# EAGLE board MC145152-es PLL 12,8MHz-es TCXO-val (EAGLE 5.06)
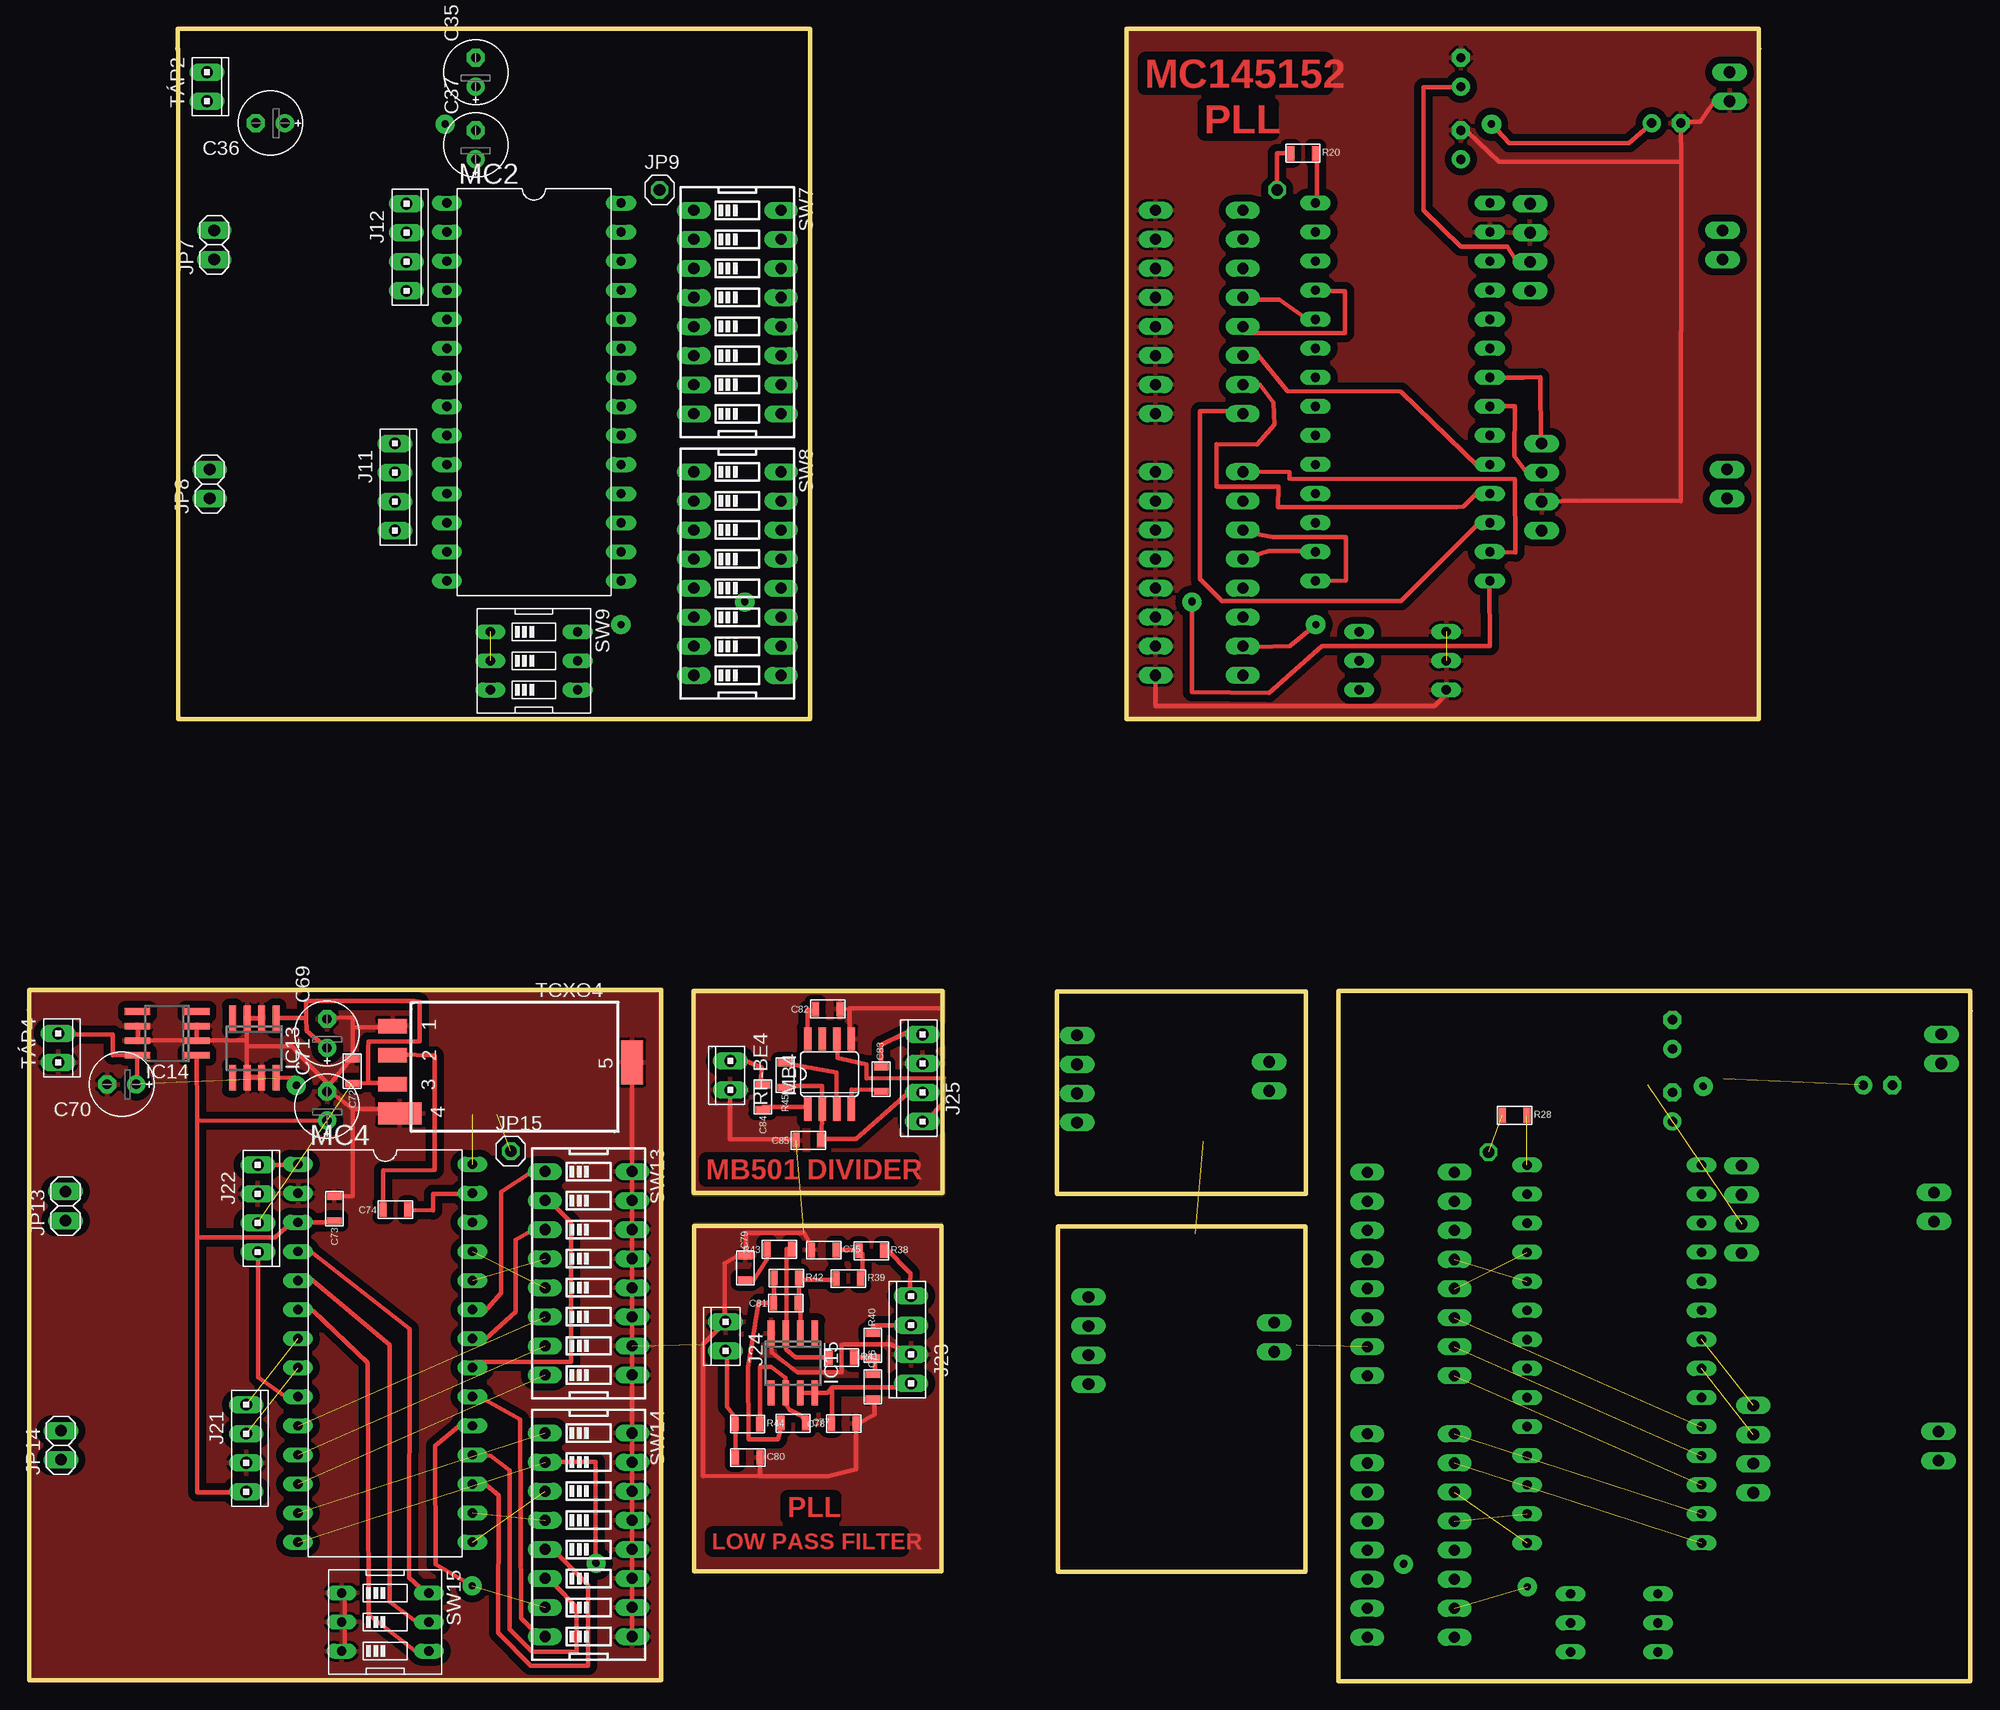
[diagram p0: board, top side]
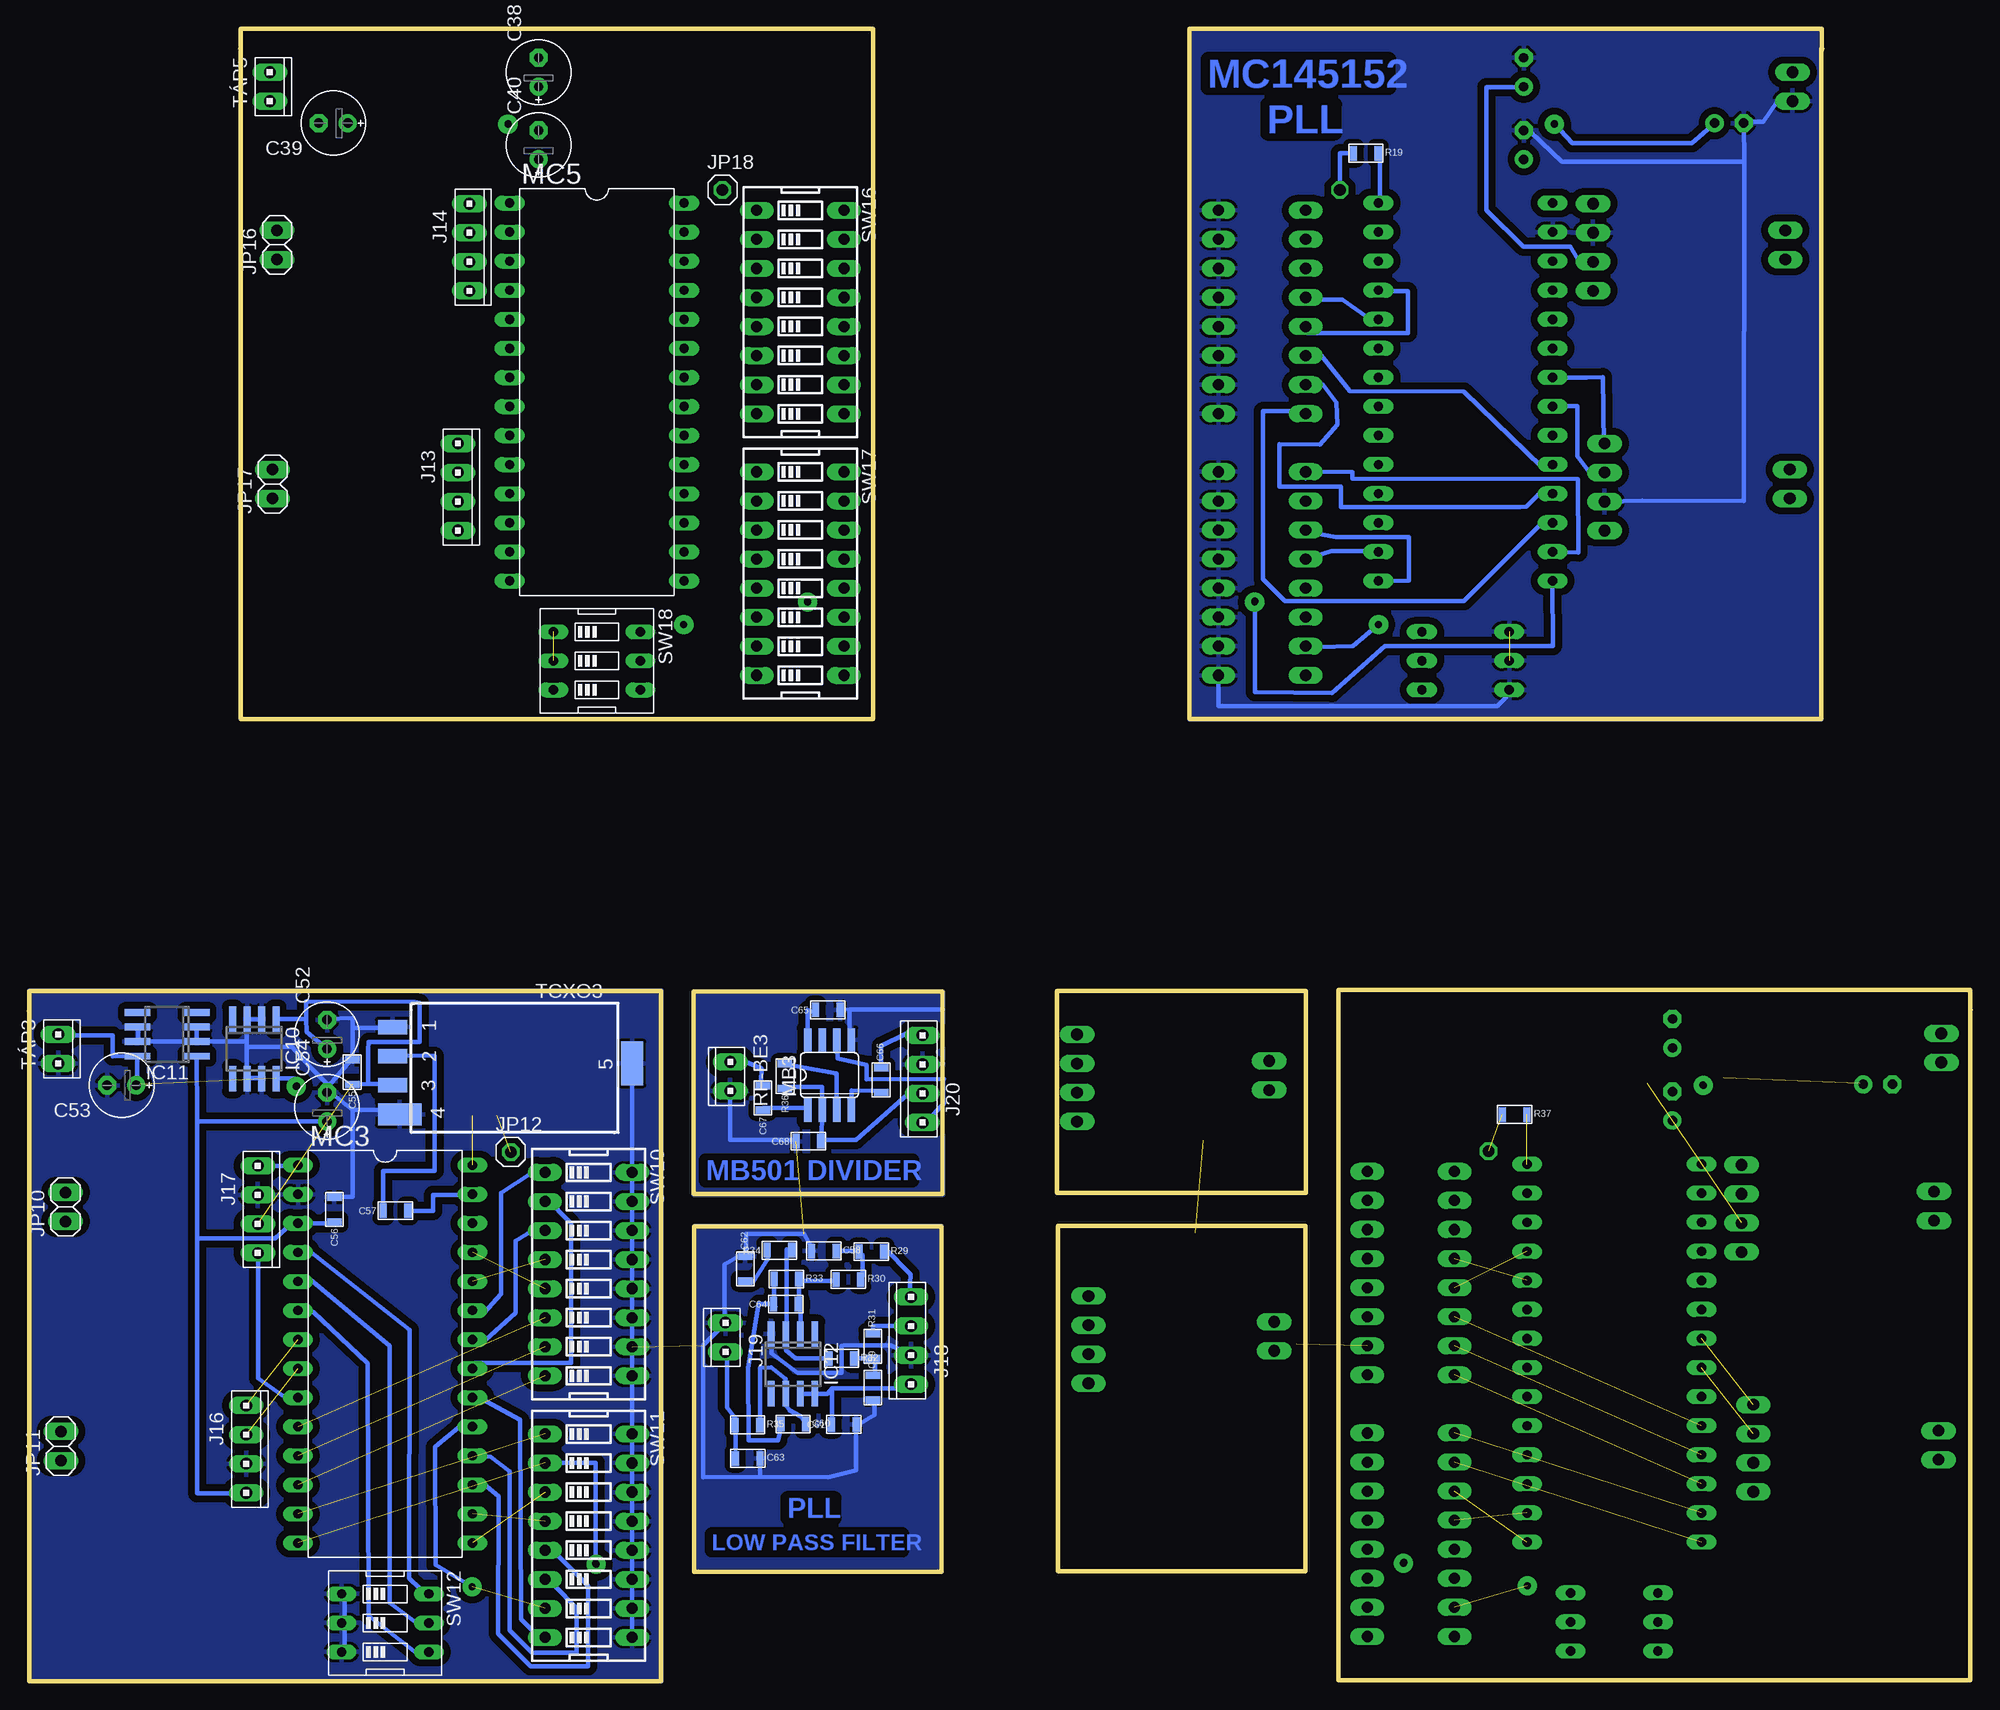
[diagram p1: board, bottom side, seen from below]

Size 169.73 x 144.42 mm. Coordinates in mm from the lower left corner, seen from the top.
Outline: 13.04,142.51 13.04,144.42 68.29,144.42 68.29,84.09
Outline: 13,142.66 13.06,142.66 13.06,84.08 68.26,84.08 68.26,84.14
Outline: 169.68,58.43 169.68,60.34 114.44,60.34 114.44,0.01
Outline: 169.73,58.58 169.67,58.58 169.67,0 114.46,0 114.46,0.06
Outline: 111.47,39.73 89.95,39.73 89.95,9.54 111.59,9.54 111.59,39.73
Outline: 111.57,60.26 89.87,60.26 89.87,42.59 111.61,42.59 111.61,60.26
Outline: 0.04,58.51 0.04,60.42 55.29,60.42 55.29,0.09
Outline: 0,58.66 0.06,58.66 0.06,0.08 55.26,0.08 55.26,0.14
Outline: 58.26,39.81 79.78,39.81 79.78,9.62 58.13,9.62 58.13,39.81
Outline: 58.16,60.33 79.86,60.33 79.86,42.67 58.12,42.67 58.12,60.33
Outline: 151.19,142.51 151.19,144.42 95.94,144.42 95.94,84.09
Outline: 151.23,142.66 151.18,142.66 151.18,84.08 95.97,84.08 95.97,84.14
Copper layers (1*16): Top 0.035mm / dielectric 1.5mm / Bottom 0.035mm
Design rules "default *": minimum track width 10mil, minimum drill 24mil, track to track 8mil, track to pad 8mil, pad to pad 8mil, via to via 8mil, smd to smd 8mil, copper to edge 0mil, drill to drill 20mil, minimum pad ring 10mil, minimum via ring 8mil, stop-mask expansion 4mil, vias tented up to drill 0mil, thermal gap 10mil

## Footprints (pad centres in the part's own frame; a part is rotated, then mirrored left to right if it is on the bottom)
E2,5-6E = drill 0.813 pad 1.575 round: + -1.27,0 | drill 0.813 pad 1.575 octagon: - 1.27,0
0805 = smd 0.635 x 1.27: P$1 1.143,0; P$2 -1.016,0
SO08 = smd 0.6 x 2.2: 1 -1.905,-2.6; 2 -0.635,-2.6; 3 0.635,-2.6; 4 1.905,-2.6; 5 1.905,2.6; 6 0.635,2.6; 7 -0.635,2.6; 8 -1.905,2.6
10X04MTA = drill 1.016 long: 1 3.81,0; 2 1.27,0; 3 -1.27,0; 4 -3.81,0
10X02MTA = drill 1.016 long: 1 1.27,0; 2 -1.27,0
1X02 = drill 1.016 long: 1 -1.27,0; 2 1.27,0
1X01 = drill 1.016 octagon: 1 0,0
SO08' = smd 0.66 x 2.032: 1 -1.905,-3.073; 2 -0.635,-3.073; 3 0.635,-3.073; 4 1.905,-3.073; 5 1.905,3.073; 6 0.635,3.073; 7 -0.635,3.073; 8 -1.905,3.073
DIL28 = drill 0.813 long: 1 -15.24,-7.62; 2 -12.7,-7.62; 3 -10.16,-7.62; 4 -7.62,-7.62; 5 -5.08,-7.62; 6 -2.54,-7.62; 7 0,-7.62; 8 2.54,-7.62; 9 5.08,-7.62; 10 7.62,-7.62; 11 10.16,-7.62; 12 12.7,-7.62; 13 15.24,-7.62; 14 17.78,-7.62; 15 17.78,7.62; 16 15.24,7.62; 17 12.7,7.62; 18 10.16,7.62; 19 7.62,7.62; 20 5.08,7.62; 21 2.54,7.62; 22 0,7.62; 23 -2.54,7.62; 24 -5.08,7.62; 25 -7.62,7.62; 26 -10.16,7.62; 27 -12.7,7.62; 28 -15.24,7.62
DIPSWITCH-08 = drill 0.97 long: 1 -8.89,-3.81; 2 -6.35,-3.81; 3 -3.81,-3.81; 4 -1.27,-3.81; 5 1.27,-3.81; 6 3.81,-3.81; 7 6.35,-3.81; 8 8.89,-3.81; 9 8.89,3.81; 10 6.35,3.81; 11 3.81,3.81; 12 1.27,3.81; 13 -1.27,3.81; 14 -3.81,3.81; 15 -6.35,3.81; 16 -8.89,3.81
EDG-03 = drill 0.813 long: 1 -2.54,-3.81; 2 0,-3.81; 3 2.54,-3.81; 4 2.54,3.81; 5 0,3.81; 6 -2.54,3.81
TCXO = smd 1.27 x 2.54: 1 -3.81,-9.525; 2 -1.27,-9.525; 3 1.27,-9.525 | smd 1.93 x 3.81: 4 3.81,-8.89 | smd 3.81 x 1.93: 5 -0.635,11.43

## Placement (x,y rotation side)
C35  10uF  [E2,5-6E]  39.08,140.61 90 top
C36  10uF  [E2,5-6E]  21.13,136.16 180 top
C37  10uF  [E2,5-6E]  39.08,134.26 90 top
C38  10uF  [E2,5-6E]  125.15,140.61 90 bottom
C39  10uF  [E2,5-6E]  143.1,136.16 180 bottom
C40  10uF  [E2,5-6E]  125.15,134.26 90 bottom
C52  10uF  [E2,5-6E]  143.65,56.53 90 bottom
C53  10uF  [E2,5-6E]  161.6,52.08 180 bottom
C54  10uF  [E2,5-6E]  143.65,50.18 90 bottom
C55  0.1uF  [0805]  141.45,53.3 270 bottom
C56  0.1uF  [0805]  143.01,41.29 270 bottom
C57  1nF  [0805]  137.6,41.12 180 bottom
C58  22nF  [0805]  100.29,37.6 0 bottom
C59  22nF  [0805]  95.95,25.59 90 bottom
C60  33nF  [0805]  102.98,22.46 0 bottom
C61  [0805]  98.42,22.44 180 bottom
C62  33nF  [0805]  107.1,35.97 90 bottom
C63  [0805]  106.95,19.47 0 bottom
C64  120pF  [0805]  103.49,32.96 180 bottom
C65  1nF  [0805]  99.83,58.66 180 bottom
C66  1nF  [0805]  95.24,52.47 90 bottom
C67  1nF  [0805]  105.57,51.03 270 bottom
C68  1nF  [0805]  101.52,47.18 180 bottom
C69  10uF  [E2,5-6E]  26.08,56.61 90 top
C70  10uF  [E2,5-6E]  8.13,52.16 180 top
C71  10uF  [E2,5-6E]  26.08,50.26 90 top
C72  0.1uF  [0805]  28.28,53.37 270 top
C73  0.1uF  [0805]  26.71,41.37 270 top
C74  1nF  [0805]  32.12,41.2 180 top
C75  22nF  [0805]  69.44,37.68 0 top
C76  22nF  [0805]  73.78,25.67 90 top
C77  33nF  [0805]  66.74,22.54 0 top
C78  [0805]  71.31,22.51 180 top
C79  33nF  [0805]  62.62,36.05 90 top
C80  [0805]  62.78,19.55 0 top
C81  120pF  [0805]  66.24,33.04 180 top
C82  1nF  [0805]  69.9,58.74 180 top
C83  1nF  [0805]  74.49,52.55 90 top
C84  1nF  [0805]  64.16,51.11 270 top
C85  1nF  [0805]  68.21,47.26 180 top
IC10  78L05SMD  [SO08]  150,55.26 180 bottom
IC11  78L08SMD  [SO08]  157.62,56.53 90 bottom
IC12  OP27D  [SO08]  102.93,27.73 180 bottom
IC13  78L05SMD  [SO08]  19.73,55.34 180 top
IC14  78L08SMD  [SO08]  12.11,56.61 90 top
IC15  OP27D  [SO08]  66.8,27.81 180 top
J11  [10X04MTA]  32.01,104.35 270 top
J12  [10X04MTA]  33.03,125.31 270 top
J13  [10X04MTA]  132.22,104.35 270 bottom
J14  [10X04MTA]  131.2,125.31 270 bottom
J16  [10X04MTA]  150.72,20.28 270 bottom
J17  [10X04MTA]  149.7,41.23 270 bottom
J18  [10X04MTA]  92.62,29.76 90 bottom
J19  [10X02MTA]  108.84,30.05 90 bottom
J20  [10X04MTA]  91.62,52.63 90 bottom
J21  [10X04MTA]  19.01,20.35 270 top
J22  [10X04MTA]  20.03,41.31 270 top
J23  [10X04MTA]  77.11,29.84 90 top
J24  [10X02MTA]  60.89,30.13 90 top
J25  [10X04MTA]  78.11,52.71 90 top
JP7  [1X02]  16.22,125.51 90 top
JP8  [1X02]  15.83,104.62 90 top
JP9  LED  [1X01]  55.14,130.32 0 top
JP10  [1X02]  166.51,41.43 90 bottom
JP11  [1X02]  166.9,20.54 90 bottom
JP12  LED  [1X01]  127.59,46.24 0 bottom
JP13  [1X02]  3.22,41.51 90 top
JP14  [1X02]  2.83,20.62 90 top
JP15  LED  [1X01]  42.14,46.32 0 top
JP16  [1X02]  148.01,125.51 90 bottom
JP17  [1X02]  148.41,104.62 90 bottom
JP18  LED  [1X01]  109.09,130.32 0 bottom
MB3  [SO08']  99.74,52.97 0 bottom
MB4  [SO08']  69.98,53.05 0 top
MC2  MC145152  [DIL28]  44.16,113.94 270 top
MC3  MC145152  [DIL28]  138.57,29.86 270 bottom
MC4  MC145152  [DIL28]  31.16,29.94 270 top
MC5  MC145152  [DIL28]  120.07,113.94 270 bottom
R19  1K  [0805]  52.94,133.52 0 bottom
R20  1K  [0805]  111.3,133.52 0 top
R28  1K  [0805]  129.79,49.44 0 top
R29  10K  [0805]  96.14,37.53 0 bottom
R30  100K  [0805]  98.16,35.11 0 bottom
R31  10K  [0805]  95.96,29.2 90 bottom
R32  100K  [0805]  98.76,28.21 0 bottom
R33  68K  [0805]  103.57,35.14 0 bottom
R34  68K  [0805]  104.05,37.65 180 bottom
R35  [0805]  106.97,22.4 0 bottom
R36  0OHM  [0805]  103.63,52.94 270 bottom
R37  1K  [0805]  39.94,49.52 0 bottom
R38  10K  [0805]  73.59,37.61 0 top
R39  100K  [0805]  71.56,35.19 0 top
R40  10K  [0805]  73.77,29.28 90 top
R41  100K  [0805]  70.97,28.28 0 top
R42  68K  [0805]  66.16,35.22 0 top
R43  68K  [0805]  65.67,37.73 180 top
R44  [0805]  62.76,22.47 0 top
R45  0OHM  [0805]  66.09,53.02 270 top
RF-BE3  [10X02MTA]  108.41,52.85 90 bottom
RF-BE4  [10X02MTA]  61.31,52.93 90 top
SW7  [DIPSWITCH-08]  61.94,119.65 270 top
SW8  [DIPSWITCH-08]  61.94,96.79 270 top
SW9  [EDG-03]  44.16,89.17 270 top
SW10  [DIPSWITCH-08]  120.79,35.57 270 bottom
SW11  [DIPSWITCH-08]  120.79,12.71 270 bottom
SW12  [EDG-03]  138.57,5.09 270 bottom
SW13  [DIPSWITCH-08]  48.94,35.65 270 top
SW14  [DIPSWITCH-08]  48.94,12.79 270 top
SW15  [EDG-03]  31.16,5.17 270 top
SW16  [DIPSWITCH-08]  102.29,119.65 270 bottom
SW17  [DIPSWITCH-08]  102.29,96.79 270 bottom
SW18  [EDG-03]  120.07,89.17 270 bottom
TCXO3  12.8MHz  [TCXO]  128.41,53.35 270 bottom
TCXO4  12.8MHz  [TCXO]  41.32,53.43 270 top
TÁP2  12V  [10X02MTA]  15.58,139.34 270 top
TÁP3  12V  [10X02MTA]  167.14,55.26 270 bottom
TÁP4  12V  [10X02MTA]  2.58,55.34 270 top
TÁP5  12V  [10X02MTA]  148.65,139.34 270 bottom
U$1  FRAMES-A4  [FRAMES-A4]  83.62,112.47 0 top

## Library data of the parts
C35-C40 C52-C54 C69-C71 = rcl
C55-C68 C72-C85 R19 R20 R28-R45 = scenix4
IC10-IC15 = linear
J11-J14 J16-J25 RF-BE3 RF-BE4 TÁP2-TÁP5 = con-amp
JP7-JP18 = pinhead-1
MB3 MB4 = MB501
MC2-MC5 = MC145152
SW7 SW8 SW10 SW11 SW13 SW14 SW16 SW17 = SparkFun-7
SW9 SW12 SW15 SW18 = special
TCXO3 TCXO4 = TCXO
U$1 = FRAME-A4

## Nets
GND2: C35.- C36.- C37.- J11.2 J12.3 MC2.2 SW7.9 SW7.10 SW7.11 SW7.12 SW7.13 SW7.14 SW7.15 SW7.16 SW8.9 SW8.10 SW8.11 SW8.12 SW8.13 SW8.14 SW8.15 SW8.16 SW9.1 SW9.2 SW9.3 TÁP2.1
GND3: C52.- C53.- C54.- C55.P$2 C56.P$2 C58.P$2 C59.P$2 C61.P$2 C62.P$1 C63.P$1 C65.P$2 C68.P$1 IC10.2 IC10.3 IC10.6 IC10.7 IC11.2 IC11.3 IC11.6 IC11.7 IC12.4 J16.2 J17.3 J18.3 J19.1 J20.2 MB3.5 MC3.2 RF-BE3.2 SW10.9 SW10.10 SW10.11 SW10.12 SW10.13 SW10.14 SW10.15 SW10.16 SW11.9 SW11.10 SW11.11 SW11.12 SW11.13 SW11.14 SW11.15 SW11.16 SW12.1 SW12.2 SW12.3 TCXO3.1 TCXO3.4 TCXO3.5 TÁP3.1
GND4: C69.- C70.- C71.- C72.P$2 C73.P$2 C75.P$2 C76.P$2 C78.P$2 C79.P$1 C80.P$1 C82.P$2 C85.P$1 IC13.2 IC13.3 IC13.6 IC13.7 IC14.2 IC14.3 IC14.6 IC14.7 IC15.4 J21.2 J22.3 J23.3 J24.1 J25.2 MB4.5 MC4.2 RF-BE4.2 SW13.9 SW13.10 SW13.11 SW13.12 SW13.13 SW13.14 SW13.15 SW13.16 SW14.9 SW14.10 SW14.11 SW14.12 SW14.13 SW14.14 SW14.15 SW14.16 SW15.1 SW15.2 SW15.3 TCXO4.1 TCXO4.4 TCXO4.5 TÁP4.1
GND5: C38.- C39.- C40.- J13.2 J14.3 MC5.2 SW16.9 SW16.10 SW16.11 SW16.12 SW16.13 SW16.14 SW16.15 SW16.16 SW17.9 SW17.10 SW17.11 SW17.12 SW17.13 SW17.14 SW17.15 SW17.16 SW18.1 SW18.2 SW18.3 TÁP5.1
N$106: C36.+
N$107: MC5.10 SW16.6
N$108: MC5.12 SW16.8
N$109: MC2.10 SW7.6
N$110: MC2.12 SW7.8
N$111: MC2.13 SW8.1
N$112: MC2.14
N$113: MC5.13 SW17.1
N$114: MC5.15 SW17.3
N$115: MC5.25 SW16.5
N$116: MC2.15 SW8.3
N$117: MC5.11 SW16.7
N$118: MC5.24 SW16.4
N$119: SW8.7
N$120: J13.4 MC5.7
N$121: MC2.25 SW7.5
N$122: MC2.11 SW7.7
N$123: MC2.24 SW7.4
N$124: J13.3 MC5.8
N$125: MC5.16 SW17.4
N$127: J11.4 MC2.7
N$128: J11.3 MC2.8
N$130: MC2.16 SW8.4
N$131: C35.+ J12.2
N$135: MC2.28 R19.P$1
N$136: JP9.1 R19.P$2
N$138: MC5.28 R20.P$1
N$139: JP18.1 R20.P$2
N$140: MC5.14
N$141: C38.+ J14.2
N$142: C39.+
N$143: SW17.7
N$158: C53.+ IC10.8 IC11.8 TÁP3.2
N$159: J17.4 MC3.1
N$160: C54.+ C56.P$1 IC11.1 J16.1 MC3.3
N$161: MC3.10 SW10.6
N$162: MC3.12 SW10.8
N$163: MC3.13 SW11.1
N$164: MC3.14 SW11.2
N$165: MC3.4 SW12.6
N$166: MC3.5 SW12.5
N$167: MC3.6 SW12.4
N$168: MC3.15 SW11.3
N$169: MC3.17 SW11.5
N$170: MC3.18 SW11.6
N$171: MC3.19 SW11.7
N$172: MC3.20 SW11.8
N$173: MC3.25 SW10.5
N$174: MC3.11 SW10.7
N$175: MC3.24 SW10.4
N$176: MC3.23 SW10.1
N$177: MC3.21 SW10.2
N$178: MC3.22 SW10.3
N$179: J16.4 MC3.7
N$180: J16.3 MC3.8
N$181: J17.1 MC3.9
N$182: MC3.16 SW11.4
N$183: C52.+ C55.P$1 IC10.1 J17.2 TCXO3.3
N$187: MC3.28 R28.P$1
N$188: JP12.1 R28.P$2
N$189: C57.P$2 MC3.27
N$190: C57.P$1 TCXO3.2
N$191: J18.1 R29.P$1
N$192: C58.P$1 R29.P$2 R30.P$1
N$193: C59.P$1 R31.P$2 R32.P$1
N$194: C64.P$2 IC12.2 R30.P$2 R33.P$1
N$195: IC12.3 R32.P$2 R34.P$2
N$196: C61.P$1 IC12.7 J18.4
N$197: C60.P$2 C64.P$1 R33.P$2
N$198: C60.P$1 IC12.6 R35.P$1
N$199: C62.P$2 R34.P$1
N$200: C63.P$2 J19.2 R35.P$2
N$201: J18.2 R31.P$1
N$202: J20.4 MB3.6
N$203: C65.P$1 MB3.8
N$204: C68.P$2 J20.3 MB3.2 R36.P$1
N$205: C66.P$1 J20.1
N$206: C66.P$2 MB3.4
N$207: C67.P$1 MB3.1
N$208: C67.P$2 RF-BE3.1
N$209: MB3.3 R36.P$2
N$210: C70.+ IC13.8 IC14.8 TÁP4.2
N$211: J22.4 MC4.1
N$212: C71.+ C73.P$1 IC14.1 J21.1 MC4.3
N$213: MC4.10 SW13.6
N$214: MC4.12 SW13.8
N$215: MC4.13 SW14.1
N$216: MC4.14 SW14.2
N$217: MC4.4 SW15.6
N$218: MC4.5 SW15.5
N$219: MC4.6 SW15.4
N$220: MC4.15 SW14.3
N$221: MC4.17 SW14.5
N$222: MC4.18 SW14.6
N$223: MC4.19 SW14.7
N$224: MC4.20 SW14.8
N$225: MC4.25 SW13.5
N$226: MC4.11 SW13.7
N$227: MC4.24 SW13.4
N$228: MC4.23 SW13.1
N$229: MC4.21 SW13.2
N$230: MC4.22 SW13.3
N$231: J21.4 MC4.7
N$232: J21.3 MC4.8
N$233: J22.1 MC4.9
N$234: MC4.16 SW14.4
N$235: C69.+ C72.P$1 IC13.1 J22.2 TCXO4.3
N$239: MC4.28 R37.P$1
N$240: JP15.1 R37.P$2
N$241: C74.P$2 MC4.27
N$242: C74.P$1 TCXO4.2
N$243: J23.1 R38.P$1
N$244: C75.P$1 R38.P$2 R39.P$1
N$245: C76.P$1 R40.P$2 R41.P$1
N$246: C81.P$2 IC15.2 R39.P$2 R42.P$1
N$247: IC15.3 R41.P$2 R43.P$2
N$248: C78.P$1 IC15.7 J23.4
N$249: C77.P$2 C81.P$1 R42.P$2
N$250: C77.P$1 IC15.6 R44.P$1
N$251: C79.P$2 R43.P$1
N$252: C80.P$2 J24.2 R44.P$2
N$253: J23.2 R40.P$1
N$254: J25.4 MB4.6
N$255: C82.P$1 MB4.8
N$256: C85.P$2 J25.3 MB4.2 R45.P$1
N$257: C83.P$1 J25.1
N$258: C83.P$2 MB4.4
N$259: C84.P$1 MB4.1
N$260: C84.P$2 RF-BE4.1
N$261: MB4.3 R45.P$2
S$1: SW17.2
S$2: TÁP2.2
S$3: TÁP5.2
S$7: SW8.2

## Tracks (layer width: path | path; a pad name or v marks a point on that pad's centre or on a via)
GND2  (1 unrouted)
  Bottom 0.254: C36.- 19.97,136.29 | SW9.3 40.6,86
  Bottom 0.406: TÁP2.1 17.02,137.93 18.14,136.29 19.97,136.29 | C37.- 38.45,135.38 35.76,132.79 21.86,132.79 19.79,132.8 | J11.2 28.69,103.16 19.85,103.1 19.79,132.8 | 19.79,132.8 C36.- | SW8.9 65.75,85.21 41.37,85.24 40.6,86
  pour Bottom (isolate 0.61): 13.06,144.4 68.27,144.4 68.27,84.05 13.06,84.05
GND3  (2 unrouted)
  Bottom 0.254: 142.12,2.68 SW12.3 | SW12.2 142.12,5.73 | 141.36,54.5 C55.P$2 141.4,54.5 | 138.31,57.07 TCXO3.1 | 143.65,57.89 C52.- | 137.55,49.92 TCXO3.4 | 150.62,52.92 IC10.6 150.47,52.71 | 150.65,57.54 IC10.3 150.47,57.82 | 154.26,55.91 IC11.2 | 159.68,55.91 IC11.7 160.16,56.06 | IC11.2 155.1,55.91 | 142.89,42.3 C56.P$2 | 160.16,57.11 IC11.6 | 149.41,52.71 IC10.7 | 155.05,57.11 IC11.3 | IC11.2 155.05,56.06 | 149.41,57.82 IC10.2 | 150.56,55.41 150.68,54.49 | 97.28,22.57 C61.P$2 97.51,22.03 97.49,22.29 | 95.83,24.49 C59.P$2 | 105.82,17.84 C63.P$1 | 108.91,31.23 J19.1 108.9,31.6 | 107.58,37.2 C62.P$1 107.03,37.25 | 101.13,37.62 C58.P$2 | 104.79,29.65 104.78,30.1 IC12.4 | 98.53,29.35 98.68,29.3 | J18.3 92.74,28.59 | 98.01,58.71 98.76,58.68 C65.P$2 | 98.01,56.12 MB3.5 | 89.8,53.97 89.82,58.71 | 91.3,53.91 J20.2 | C68.P$1 102.9,47.29 | 108.44,51.29 RF-BE3.2
  Bottom 0.406: SW11.9 SW11.10 SW11.11 SW11.12 SW11.13 SW11.14 SW11.15 SW11.16 SW10.9 SW10.10 SW10.11 SW10.12 SW10.13 SW10.14 SW10.15 SW10.16 TCXO3.5 | 142.12,2.68 142.12,4.97 SW12.2 | 142.12,5.73 142.12,7.25 SW12.1 | 143.72,51.74 143.65,52.21 | 143.72,51.74 141.36,54.5 | 141.4,57.07 138.31,57.07 | 141.4,54.5 141.4,57.07 | 143.65,57.89 141.4,57.94 141.4,57.07 | 141.41,49.92 142.02,50.41 143.72,51.74 | 141.41,49.92 137.55,49.92 | 150.65,55.91 150.65,57.54 | 150.65,55.91 150.68,54.49 150.62,52.92 | 150.65,55.91 152.91,55.89 153.05,55.91 154.26,55.91 | 155.1,55.91 159.68,55.91 | 142.89,42.3 141.41,42.32 141.41,49.92 | 160.16,56.06 160.16,57.11 | 150.47,52.71 149.41,52.71 | 155.05,56.06 155.05,57.11 | 150.47,57.82 149.41,57.82 | 150.56,55.41 146.72,55.41 145.17,53.73 143.65,52.21 | 143.65,52.21 C54.- | 95.83,24.49 95.82,23.26 97.49,22.29 | 105.82,17.84 99.89,17.83 97.41,18.45 C61.P$2 | 108.91,31.23 110.8,29.35 110.78,17.82 105.81,17.85 C63.P$1 | 107.58,37.2 108.93,36.43 108.9,31.6 | 101.13,37.62 101.96,39.08 107.03,39.09 107.03,37.25 | 104.79,29.65 104.79,28.64 102.52,26.92 98.7,26.93 98.68,29.3 | 98.53,29.35 94.39,29.35 92.74,28.59 | 98.01,56.12 98.01,58.71 89.82,58.71 | 91.3,53.91 89.8,53.97 | 102.9,47.29 108.44,47.29 108.44,51.29
  pour Bottom (isolate 0.61): 169.66,60.36 114.43,60.36 114.43,-0.01 169.66,-0.01
  pour Bottom (isolate 0.61): 111.47,39.79 89.95,39.79 89.95,9.54 111.59,9.54 111.59,39.73
  pour Bottom (isolate 0.61): 89.83,60.22 89.83,42.51 111.62,42.51 111.62,60.28
GND4  (2 unrouted)
  Top 0.254: SW15.3 27.6,2.76 | SW15.2 27.6,5.81 | 28.37,54.58 C72.P$2 28.33,54.58 | 31.41,57.15 TCXO4.1 | 26.08,57.97 C69.- | 32.18,50 TCXO4.4 | 19.11,52.99 IC13.6 19.26,52.79 | 19.08,57.62 IC13.3 19.26,57.9 | IC14.2 15.47,55.98 | 10.05,55.98 IC14.7 9.57,56.14 | 14.62,55.98 IC14.2 | 26.84,42.38 C73.P$2 | 9.57,57.19 IC14.6 | 20.31,52.79 IC13.7 | 14.68,57.19 IC14.3 | IC14.2 14.68,56.14 | 20.31,57.9 IC13.2 | 19.05,54.57 19.16,55.49 | 72.45,22.65 C78.P$2 72.21,22.11 72.24,22.37 | 73.9,24.57 C76.P$2 | C80.P$1 63.91,17.92 | 60.81,31.31 J24.1 60.83,31.68 | 62.15,37.28 C79.P$1 62.69,37.33 | 68.6,37.7 C75.P$2 | 64.93,29.73 64.95,30.18 IC15.4 | 71.05,29.38 71.2,29.43 | 76.99,28.67 J23.3 | 71.72,58.79 70.96,58.76 C82.P$2 | 71.72,56.2 MB4.5 | 79.9,58.79 79.92,54.05 | 78.43,53.99 J25.2 | 66.83,47.36 C85.P$1 | 61.29,51.37 RF-BE4.2
  Top 0.406: SW14.9 SW14.10 SW14.11 SW14.12 SW14.13 SW14.14 SW14.15 SW14.16 SW13.9 SW13.10 SW13.11 SW13.12 SW13.13 SW13.14 SW13.15 SW13.16 TCXO4.5 | 27.6,2.76 27.6,5.05 SW15.2 | 27.6,5.81 27.6,7.33 SW15.1 | 26.08,52.29 26.01,51.82 | 26.01,51.82 28.37,54.58 | 28.33,57.15 31.41,57.15 | 28.33,54.58 28.33,57.15 | 26.08,57.97 28.33,58.02 28.33,57.15 | 28.32,50 27.71,50.49 26.01,51.82 | 28.32,50 32.18,50 | 19.08,55.98 19.08,57.62 | 19.08,55.98 19.05,54.57 19.11,52.99 | 19.08,55.98 16.82,55.97 16.68,55.98 15.47,55.98 | 10.05,55.98 14.62,55.98 | 26.84,42.38 28.32,42.4 28.32,50 | 9.57,56.14 9.57,57.19 | 19.26,52.79 20.31,52.79 | 14.68,56.14 14.68,57.19 | 19.26,57.9 20.31,57.9 | 19.16,55.49 23.01,55.49 24.56,53.81 26.08,52.29 | 26.08,52.29 C71.- | 73.9,24.57 73.91,23.34 72.24,22.37 | 63.91,17.92 69.84,17.91 72.32,18.53 C78.P$2 | 60.81,31.31 58.93,29.43 58.95,17.9 63.92,17.93 C80.P$1 | 62.15,37.28 60.8,36.51 60.83,31.68 | 68.6,37.7 67.77,39.16 62.69,39.17 62.69,37.33 | 64.93,29.73 64.93,28.72 67.21,27 71.02,27.01 71.05,29.38 | 71.2,29.43 75.34,29.43 76.99,28.67 | 71.72,56.2 71.72,58.79 79.9,58.79 | 79.92,54.05 78.43,53.99 | 66.83,47.36 61.29,47.36 61.29,51.37
  pour Top (isolate 0.61): 0.07,60.44 55.3,60.44 55.3,0.07 0.07,0.07
  pour Top (isolate 0.61): 58.25,39.87 79.78,39.87 79.78,9.62 58.13,9.62 58.13,39.81
  pour Top (isolate 0.61): 79.9,60.3 79.9,42.59 58.11,42.59 58.11,60.36
GND5  (1 unrouted)
  Top 0.254: C39.- 144.26,136.29 | 123.63,86 SW18.3
  Top 0.406: TÁP5.1 147.21,137.93 146.09,136.29 144.26,136.29 | C40.- 125.78,135.38 128.47,132.79 142.37,132.79 144.44,132.8 | J13.2 135.54,103.16 144.38,103.1 144.44,132.8 | 144.44,132.8 C39.- | SW17.9 98.48,85.21 122.87,85.24 123.63,86
  pour Top (isolate 0.61): 151.18,144.4 95.96,144.4 95.96,84.05 151.18,84.05
N$106  (via drill 0.61)
  Bottom 0.406: v36.42,136.11 34.83,134.4 24.38,134.4 C36.+
N$107
  Top 0.406: MC5.10 126.75,106.09 119.92,112.69 109.99,112.75 107.46,115.85 SW16.6
N$108
  Top 0.254: 105.28,110.97 SW16.8
  Top 0.406: 105.28,110.97 102.35,110.97 102.35,96.33 104.3,94.38 119.92,94.38 126.75,101.21 MC5.12
N$109
  Bottom 0.406: MC2.10 37.48,106.09 44.31,112.69 54.24,112.75 56.77,115.85 SW7.6
N$110
  Bottom 0.254: 58.95,110.97 SW7.8
  Bottom 0.406: 58.95,110.97 61.88,110.97 61.88,96.33 59.93,94.38 44.31,94.38 37.48,101.21 MC2.12
N$111
  Bottom 0.254: SW8.1 58.13,105.05
  Bottom 0.406: MC2.13 34.31,98.61 34.35,105.07 54.04,105.07 54.05,105.68 SW8.1
N$112  (via drill 0.61)
  Bottom 0.406: v62.57,94.37 62.58,86.43 55.86,86.34 51.21,90.47 36.53,90.47 36.56,96.16 MC2.14
N$113
  Top 0.254: SW17.1 106.1,105.05
  Top 0.406: MC5.13 129.92,98.61 129.88,105.07 110.19,105.07 110.19,105.68 SW17.1
N$114
  Top 0.254: SW17.3 106.1,100.48
  Top 0.406: 106.1,100.48 108.74,99.97 115.11,99.97 115.13,96.16 MC5.15
N$115
  Top 0.254: SW16.5 106.25,117.8
  Top 0.406: 106.25,117.8 115.04,117.8 115.04,121.48 113.09,121.48 MC5.25
N$116
  Bottom 0.254: 58.13,100.48 SW8.3
  Bottom 0.406: 58.13,100.48 55.49,99.97 49.12,99.97 49.1,96.16 MC2.15
N$117
  Top 0.406: SW16.7 107.6,113.3 108.79,111.75 108.87,109.81 107.34,108.05 103.82,108.11 103.82,105.05 103.8,104.4 109.2,104.38 109.18,102.58 124.81,102.61 125.4,102.63 126.58,103.81 127.72,103.81 MC5.11
N$118
  Top 0.254: 112.11,118.78 MC5.24 | SW16.4 106.25,120.73
  Top 0.406: 112.11,118.78 109.3,120.73 106.25,120.73
N$119  (via drill 0.61)
  Bottom 0.254: 58.47,90.63 SW8.7
  Bottom 0.406: 58.47,90.63 57.02,90.38 54,90.47 v51.75,92.34
N$120
  Top 0.254: 127.73,113.9 MC5.7
  Top 0.406: 127.73,113.9 130.66,113.9 132.09,113.96 132.15,108.04 J13.4
N$121
  Bottom 0.254: 57.98,117.8 SW7.5
  Bottom 0.406: 57.98,117.8 49.19,117.8 49.19,121.48 51.15,121.48 MC2.25
N$122
  Bottom 0.406: SW7.7 56.64,113.3 55.44,111.75 55.36,109.81 56.89,108.05 60.42,108.11 60.42,105.05 60.43,104.4 55.04,104.38 55.06,102.58 39.42,102.61 38.83,102.63 37.66,103.81 36.51,103.81 MC2.11
N$123
  Bottom 0.254: 52.12,118.78 MC2.24 | 57.98,120.73 SW7.4
  Bottom 0.406: 52.12,118.78 54.93,120.73 57.98,120.73
N$124
  Top 0.254: 127.73,111.43 MC5.8 | 133.22,105.69 J13.3
  Top 0.406: MC5.8 129.1,111.43 | 127.73,111.43 129.86,111.43 129.85,107.07 130.83,105.69 133.22,105.69
N$125
  Top 0.254: 111.48,98.74 MC5.16
  Top 0.406: 111.48,98.74 108.34,98.74 SW17.4
N$126  (via drill 0.6 pad 1.68)
  other vias: 112.47,92.34
N$127
  Bottom 0.254: 36.5,113.9 MC2.7
  Bottom 0.406: 36.5,113.9 33.57,113.9 32.14,113.96 32.08,108.04 J11.4
N$128
  Bottom 0.254: 36.5,111.43 MC2.8 | J11.3 31.01,105.69
  Bottom 0.406: MC2.8 35.13,111.43 | 36.5,111.43 34.37,111.43 34.38,107.07 33.4,105.69 31.01,105.69
N$129  (via drill 0.6 pad 1.68)
  other vias: 101.65,94.29
N$130
  Bottom 0.254: MC2.16 52.76,98.74
  Bottom 0.406: 52.76,98.74 55.89,98.74 SW8.4
N$131
  Bottom 0.254: 39.43,139.28 C35.+ | J12.2 34.33,124.28
  Bottom 0.406: 39.43,139.28 42.36,139.28 42.36,128.54 39.09,125.35 35.01,125.35 34.33,124.28
N$132  (via drill 0.6 pad 1.68)
  other vias: 51.76,92.34
N$133  (via drill 0.6 pad 1.68)
  other vias: 62.58,94.29
N$134  (via drill 0.6 pad 1.68)
  other vias: 36.39,136.05
N$135
  Bottom 0.406: R19.P$1 51.65,133.52 51.65,129.7 51.78,129.7 MC2.28
N$136
  Bottom 0.406: R19.P$2 55.14,133.52 JP9.1
N$137  (via drill 0.6 pad 1.68)
  other vias: 127.84,136.05
N$138
  Top 0.406: R20.P$1 112.58,133.52 112.58,129.7 112.45,129.7 MC5.28
N$139
  Top 0.406: R20.P$2 109.09,133.52 JP18.1
N$140  (via drill 0.61)
  Top 0.406: v101.67,94.37 101.65,86.43 108.37,86.34 113.02,90.47 127.7,90.47 127.67,96.16 MC5.14
N$141
  Top 0.254: 124.8,139.28 C38.+ | 129.9,124.28 J14.2
  Top 0.406: 124.8,139.28 121.87,139.28 121.87,128.54 125.15,125.35 129.23,125.35 129.9,124.28
N$142  (via drill 0.61)
  Top 0.406: v127.82,136.11 129.4,134.4 139.85,134.4 C39.+
N$143  (via drill 0.61)
  Top 0.254: SW17.7 105.76,90.63
  Top 0.406: 105.76,90.63 107.21,90.38 110.24,90.47 v112.48,92.34
N$158  (via drill 0.61)  (1 unrouted)
  Bottom 0.254: 160.01,54.65 160.41,54.5 IC11.8 | 160.01,52.15 C53.+ | 166.57,56.42 TÁP3.2
  Bottom 0.406: 166.57,56.42 162.39,56.42 162.39,54.6 160.01,54.65 | v146.31,52.04 146.48,52.67 IC10.8 | 160.01,52.15 160.22,52.15 IC11.8
N$159
  Bottom 0.254: 146.11,45.1 MC3.1 146.54,45.04 | J17.4 149.47,45.04
  Bottom 0.406: MC3.1 146.73,45.09 | J17.4 149.04,45.1 | 149.47,45.04 146.54,45.04
N$160
  Bottom 0.254: 142.89,40.02 C56.P$1 | 152.2,16.41 J16.1 | 155.02,49.39 155.01,49.34 | 147.2,39.58 146.23,39.58 MC3.3
  Bottom 0.406: MC3.3 142.89,40.02 | IC11.1 155.02,49.39 155.02,48.9 C54.+ | 152.2,16.41 155.01,16.41 155,38.68 | 155,38.68 155.01,46.42 155.01,47.34 155.01,48.31 155.01,49.34 | 147.2,39.58 148.17,38.68 155,38.68
N$161  (1 unrouted)
N$162  (1 unrouted)
N$163  (1 unrouted)
N$164  (via drill 0.61)  (1 unrouted)
  Bottom 0.406: v120.16,10.29 120.16,19.08 123.77,19.08 SW11.2
N$165
  Bottom 0.406: SW12.6 135.55,8.11 136.47,8.98 136.44,30.71 145.25,37.63 MC3.4
N$166
  Bottom 0.406: SW12.5 135.72,5.02 138.19,6.86 138.18,29.3 145.14,35.1 MC3.5
N$167
  Bottom 0.406: SW12.4 135.67,2.32 140.03,5.7 140.08,27.76 144.85,32.29 MC3.6
N$168  (1 unrouted)
N$169
  Bottom 0.254: 129.97,17.25 MC3.17
  Bottom 0.406: 129.97,17.25 128.65,16.16 128.71,4.15 125.84,1.28 120.84,1.28 120.84,8.34 123.77,11.27 SW11.5
N$170
  Bottom 0.406: MC3.18 129.34,19.6 127.68,18.33 127.68,4.44 125.73,2.49 121.82,2.49 121.82,6.39 123.77,8.34 SW11.6
N$171  (via drill 0.61)  (1 unrouted)
  Bottom 0.406: MC3.19 132.14,22.2 134.21,20.48 134.15,10.15 v130.97,8.26
N$172
  Bottom 0.406: MC3.20 130.61,24.94 126.76,22.82 126.7,5.42 124.75,3.46 SW11.8
N$173  (1 unrouted)
N$174  (1 unrouted)
N$175  (1 unrouted)
N$176
  Bottom 0.254: 125.78,44.41 SW10.1
  Bottom 0.406: 125.78,44.41 128.42,42.69 128.43,33.85 129.92,32.17 MC3.23
N$177
  Bottom 0.254: 130.69,27.83 MC3.21 | 124.6,42.3 SW10.2
  Bottom 0.406: 130.69,27.83 122.31,27.83 122.31,40.02 124.6,42.3
N$178
  Bottom 0.254: 125.84,39.29 SW10.3
  Bottom 0.406: 125.84,39.29 127.17,38.49 127.16,32.18 129.8,29.82 MC3.22
N$179  (1 unrouted)
  Bottom 0.406: 146.19,29.9 MC3.7 146.19,29.85
N$180  (1 unrouted)
N$181
  Bottom 0.254: 149.67,37.63 J17.1
  Bottom 0.406: MC3.9 147.57,25 149.67,26.48 149.67,37.63
N$182  (1 unrouted)
N$183  (1 unrouted)
  Bottom 0.254: 138.31,52.21 TCXO3.3 | 147.99,57.88 IC10.1
  Bottom 0.406: 140.04,52.18 138.31,52.21 | C55.P$1 140.04,52.18 | 145.46,57.89 147.99,57.88 | 145.46,57.89 145.43,56.72 C52.+ | 140.04,52.18 140.06,55.23 140.02,55.85 135.57,55.85 135.57,59.28 135.99,59.35 145.46,59.38 145.46,57.89
N$184  (via drill 0.6 pad 1.68)
  other vias: 130.97,8.26
N$185  (via drill 0.6 pad 1.68)
  other vias: 120.15,10.21
N$186  (via drill 0.6 pad 1.68)
  other vias: 146.33,51.97
N$187  (1 unrouted)
N$188  (1 unrouted)
N$189
  Bottom 0.406: C57.P$2 134.4,41.08 134.38,42.51 131.58,42.51 MC3.27
N$190
  Bottom 0.254: TCXO3.2 137.5,54.68
  Bottom 0.406: 137.5,54.68 134.23,54.62 134.23,44.58 138.76,44.58 C57.P$1
N$191
  Bottom 0.254: 94.9,37.81 R29.P$1 | J18.1 92.74,33.86
  Bottom 0.406: 94.9,37.81 92.64,35.55 92.74,33.86
N$192
  Bottom 0.254: 99.13,37.62 C58.P$1 | 97.25,37.62 R29.P$2 96.88,37.25 | R30.P$1 96.88,35.37
  Bottom 0.406: 97.25,37.62 99.13,37.62 | 96.88,35.37 96.88,37.25
N$193
  Bottom 0.254: 96.12,26.71 C59.P$1 95.75,26.71 | 97.63,28.22 R32.P$1 | 96.12,28.22 R31.P$2 95.75,28.22
  Bottom 0.406: 96.12,28.22 97.63,28.22 | 95.75,26.71 95.75,28.22
N$194
  Bottom 0.254: C64.P$2 102.14,33.11 | 102.14,30.48 IC12.2 102.25,31 | C64.P$2 102.14,32.73 | 102.42,33.11 C64.P$2 | 102.42,34.99 R33.P$1 102.14,34.99 | C64.P$2 102.28,33.29 | 99.13,34.99 R30.P$2
  Bottom 0.406: 102.42,34.99 102.42,33.11 | 102.28,33.29 102.25,31 | 99.13,34.99 102.14,34.99
N$195
  Bottom 0.254: 103.54,29.64 103.54,29.97 IC12.3 103.49,30.51 | R32.P$2 99.89,28.22 | 103.5,37.72 R34.P$2
  Bottom 0.406: 99.89,28.22 102.7,28.22 103.56,28.91 103.54,29.64 | 103.49,30.51 103.5,37.72
N$196
  Bottom 0.254: 99.93,21.96 C61.P$1 99.52,22.24 | J18.4 92.74,25.58
  Bottom 0.406: IC12.7 99.93,25.12 99.52,25.6 | 99.52,25.6 99.52,22.24 | 99.52,25.6 97.25,25.59 96.5,25.58 92.74,25.58
N$197
  Bottom 0.254: 103.94,22.27 C60.P$2 | 104.4,32.73 C64.P$1 104.57,33.14 | 104.57,35.02 R33.P$2
  Bottom 0.406: 103.94,22.27 104.26,21.05 106.83,21.05 106.85,27.35 105.93,32.96 C64.P$1 | 104.57,33.14 104.57,35.02
N$198
  Bottom 0.254: C60.P$1 102.29,23.14 | 103.54,24.1 IC12.6 103.58,25.21 | 105.83,23.05 R35.P$1
  Bottom 0.406: 102.29,23.14 103.24,23.65 103.54,24.1 | 105.83,23.05 105.83,27.39 104.85,27.41 103.58,26.42 103.58,25.21
N$199
  Bottom 0.254: 106.37,34.96 C62.P$2 | 105.15,37.62 R34.P$1
  Bottom 0.406: 106.37,34.96 105.15,36.87 105.15,37.62
N$200
  Bottom 0.254: 107.93,22.94 R35.P$2 107.97,22.57 | 108.71,28.79 J19.2 | C63.P$2 107.97,20.27
  Bottom 0.406: 107.93,22.94 108.71,23.91 108.71,28.79 | 107.97,20.27 107.97,22.57
N$201
  Bottom 0.254: 92.94,31.03 92.74,30.85 J18.2
  Bottom 0.406: 92.94,31.03 95.94,31.03 R31.P$1
N$202
  Bottom 0.254: 99.17,55 99.16,55.13 99.14,55.75 MB3.6 | 99.17,55 99.18,54.94 | 89.73,50.48 89.73,52.64 | 91.24,48.97 J20.4 | 99.04,54.96 99.14,54.99 99.17,55 | 96.51,52.6 96.51,52.74
  Bottom 0.406: 96.51,52.6 89.73,52.64 | 91.24,48.97 89.73,50.48 | 99.04,54.96 99.02,54.4 96.51,53.84 96.51,52.74
N$203
  Bottom 0.254: 101.02,58.38 C65.P$1 | MB3.8 101.64,56.12
  Bottom 0.406: 101.02,58.38 101.64,58.64 101.64,56.12
N$204
  Bottom 0.254: 100.45,47.32 100.27,47.47 C68.P$2 | 100.39,49.78 MB3.2 100.37,50.1 | J20.3 92.58,51.59 | 103.25,51.94 R36.P$1
  Bottom 0.406: 100.39,49.78 100.45,47.32 97.43,47.31 92.58,51.59 | 103.25,51.94 100.4,51.94 100.37,50.1
N$205
  Bottom 0.254: 93.08,56.57 91.62,56.12 J20.1
  Bottom 0.406: 93.08,56.57 95.22,55.52 C66.P$1
N$206
  Bottom 0.254: C66.P$2 95.33,51.58 | 97.81,50.1 MB3.4
  Bottom 0.406: 95.33,51.58 97.8,51.61 97.81,50.1
N$207
  Bottom 0.254: 105.54,50.1 C67.P$1 | MB3.1 101.77,50.1
  Bottom 0.406: 101.77,50.1 105.54,50.1
N$208
  Bottom 0.254: C67.P$2 105.7,52.39 | 108.08,54.56 RF-BE3.1
  Bottom 0.406: 105.7,52.39 105.7,53.57 108.08,54.56
N$209
  Bottom 0.254: 103.28,53.86 R36.P$2 | MB3.3 99.14,50.1
  Bottom 0.406: 103.28,53.86 99.14,53.1 99.14,50.1
N$210  (via drill 0.61)  (1 unrouted)
  Top 0.254: 9.72,54.73 9.32,54.58 IC14.8 | 9.72,52.23 C70.+ | TÁP4.2 3.16,56.5
  Top 0.406: 3.16,56.5 7.33,56.5 7.33,54.68 9.72,54.73 | v23.42,52.11 23.25,52.75 IC13.8 | 9.72,52.23 9.51,52.23 IC14.8
N$211
  Top 0.254: 23.62,45.18 MC4.1 23.19,45.11 | J22.4 20.26,45.11
  Top 0.406: MC4.1 23,45.17 | J22.4 20.69,45.18 | 20.26,45.11 23.19,45.11
N$212
  Top 0.254: 26.84,40.1 C73.P$1 | 17.52,16.49 J21.1 | 14.72,49.42 14.71,49.47 | 22.53,39.66 23.5,39.66 MC4.3
  Top 0.406: MC4.3 26.84,40.1 | IC14.1 14.71,49.47 14.71,48.98 C71.+ | 17.52,16.49 14.72,16.49 14.73,38.76 | 14.73,38.76 14.72,46.49 14.71,47.41 14.71,48.39 14.72,49.42 | 22.53,39.66 21.56,38.76 14.73,38.76
N$213  (1 unrouted)
N$214  (1 unrouted)
N$215  (1 unrouted)
N$216  (via drill 0.61)  (1 unrouted)
  Top 0.406: v49.57,10.37 49.57,19.16 45.95,19.16 SW14.2
N$217
  Top 0.406: SW15.6 34.18,8.19 33.26,9.05 33.29,30.79 24.48,37.71 MC4.4
N$218
  Top 0.406: SW15.5 34.01,5.09 31.54,6.94 31.55,29.38 24.59,35.18 MC4.5
N$219
  Top 0.406: SW15.4 34.06,2.39 29.7,5.78 29.65,27.83 24.88,32.37 MC4.6
N$220  (1 unrouted)
N$221
  Top 0.254: 39.76,17.33 MC4.17
  Top 0.406: 39.76,17.33 41.07,16.23 41.02,4.23 43.89,1.36 48.88,1.36 48.88,8.42 45.95,11.35 SW14.5
N$222
  Top 0.406: MC4.18 40.38,19.68 42.05,18.41 42.05,4.52 44,2.57 47.91,2.57 47.91,6.47 45.95,8.42 SW14.6
N$223  (via drill 0.61)  (1 unrouted)
  Top 0.406: MC4.19 37.59,22.28 35.52,20.56 35.58,10.23 v38.75,8.34
N$224
  Top 0.406: MC4.20 39.12,25.02 42.97,22.9 43.03,5.49 44.98,3.54 SW14.8
N$225  (1 unrouted)
N$226  (1 unrouted)
N$227  (1 unrouted)
N$228
  Top 0.254: 43.95,44.49 SW13.1
  Top 0.406: 43.95,44.49 41.31,42.77 41.3,33.93 39.81,32.25 MC4.23
N$229
  Top 0.254: MC4.21 39.03,27.91 | 45.13,42.38 SW13.2
  Top 0.406: 39.03,27.91 47.42,27.91 47.42,40.1 45.13,42.38
N$230
  Top 0.254: 43.89,39.37 SW13.3
  Top 0.406: 43.89,39.37 42.56,38.57 42.57,32.25 39.93,29.9 MC4.22
N$231  (1 unrouted)
  Top 0.406: 23.54,29.98 MC4.7 23.54,29.92
N$232  (1 unrouted)
N$233
  Top 0.254: 20.05,37.71 J22.1
  Top 0.406: MC4.9 22.16,25.08 20.05,26.56 20.05,37.71
N$234  (1 unrouted)
N$235  (1 unrouted)
  Top 0.254: 31.41,52.29 TCXO4.3 | 21.74,57.96 IC13.1
  Top 0.406: 29.69,52.26 31.41,52.29 | C72.P$1 29.69,52.26 | 24.27,57.97 21.74,57.96 | 24.27,57.97 24.3,56.8 C69.+ | 29.69,52.26 29.67,55.31 29.71,55.93 34.16,55.93 34.16,59.36 33.74,59.43 24.27,59.46 24.27,57.97
N$236  (via drill 0.6 pad 1.68)
  other vias: 38.76,8.34
N$237  (via drill 0.6 pad 1.68)
  other vias: 49.58,10.29
N$238  (via drill 0.6 pad 1.68)
  other vias: 23.39,52.05
N$239  (1 unrouted)
N$240  (1 unrouted)
N$241
  Top 0.406: C74.P$2 35.33,41.16 35.34,42.59 38.15,42.59 MC4.27
N$242
  Top 0.254: 32.23,54.76 TCXO4.2
  Top 0.406: 32.23,54.76 35.5,54.7 35.5,44.66 30.97,44.66 C74.P$1
N$243
  Top 0.254: 74.83,37.89 R38.P$1 | J23.1 76.99,33.94
  Top 0.406: 74.83,37.89 77.09,35.63 76.99,33.94
N$244
  Top 0.254: C75.P$1 70.59,37.7 | 72.48,37.7 R38.P$2 72.85,37.33 | 72.85,35.44 R39.P$1
  Top 0.406: 70.59,37.7 72.48,37.7 | 72.85,37.33 72.85,35.44
N$245
  Top 0.254: 73.6,26.79 C76.P$1 73.98,26.79 | 72.1,28.3 R41.P$1 | 73.6,28.3 R40.P$2 73.98,28.3
  Top 0.406: 73.6,28.3 72.1,28.3 | 73.98,26.79 73.98,28.3
N$246
  Top 0.254: C81.P$2 67.59,33.19 | 67.59,30.55 IC15.2 67.48,31.08 | C81.P$2 67.59,32.81 | C81.P$2 67.31,33.19 | 67.31,35.07 R42.P$1 67.59,35.07 | 67.44,33.37 C81.P$2 | 70.59,35.07 R39.P$2
  Top 0.406: 67.31,33.19 67.31,35.07 | 67.48,31.08 67.44,33.37 | 67.59,35.07 70.59,35.07
N$247
  Top 0.254: 66.19,29.72 66.19,30.04 IC15.3 66.23,30.59 | 69.84,28.3 R41.P$2 | 66.23,37.8 R43.P$2
  Top 0.406: 69.84,28.3 67.03,28.3 66.17,28.99 66.19,29.72 | 66.23,30.59 66.23,37.8
N$248
  Top 0.254: 69.8,22.04 C78.P$1 70.2,22.32 | 76.99,25.66 J23.4
  Top 0.406: IC15.7 69.8,25.2 70.2,25.68 | 70.2,22.32 70.2,25.68 | 70.2,25.68 72.48,25.67 73.23,25.66 76.99,25.66
N$249
  Top 0.254: 65.79,22.35 C77.P$2 | 65.33,32.81 C81.P$1 65.16,33.22 | 65.16,35.1 R42.P$2
  Top 0.406: 65.79,22.35 65.47,21.13 62.9,21.13 62.87,27.43 63.8,33.04 C81.P$1 | 65.16,33.22 65.16,35.1
N$250
  Top 0.254: 67.44,23.22 C77.P$1 | 66.19,24.18 IC15.6 66.15,25.29 | R44.P$1 63.9,23.13
  Top 0.406: 67.44,23.22 66.49,23.73 66.19,24.18 | 63.9,23.13 63.9,27.47 64.87,27.48 66.14,26.5 66.15,25.29
N$251
  Top 0.254: C79.P$2 63.35,35.04 | 64.58,37.7 R43.P$1
  Top 0.406: 63.35,35.04 64.58,36.95 64.58,37.7
N$252
  Top 0.254: 61.8,23.02 R44.P$2 61.76,22.65 | 61.02,28.87 J24.2 | C80.P$2 61.76,20.35
  Top 0.406: 61.8,23.02 61.02,23.99 61.02,28.87 | 61.76,20.35 61.76,22.65
N$253
  Top 0.254: 76.79,31.11 76.99,30.93 J23.2
  Top 0.406: 76.79,31.11 73.78,31.11 R40.P$1
N$254
  Top 0.254: 70.55,55.08 70.57,55.21 70.59,55.82 MB4.6 | 70.55,55.08 70.55,55.02 | 79.99,52.72 79.99,50.56 | 78.49,49.05 J25.4 | 70.69,55.03 70.59,55.07 70.55,55.08 | 73.22,52.82 73.22,52.68
  Top 0.406: 73.22,52.68 79.99,52.72 | 79.99,50.56 78.49,49.05 | 70.69,55.03 70.7,54.48 73.22,53.92 73.22,52.82
N$255
  Top 0.254: 68.71,58.46 C82.P$1 | MB4.8 68.09,56.2
  Top 0.406: 68.71,58.46 68.09,58.72 68.09,56.2
N$256
  Top 0.254: 69.28,47.4 69.46,47.55 C85.P$2 | 69.34,49.86 MB4.2 69.36,50.18 | 77.15,51.67 J25.3 | 66.48,52.02 R45.P$1
  Top 0.406: 69.34,49.86 69.28,47.4 72.3,47.39 77.15,51.67 | 66.48,52.02 69.32,52.02 69.36,50.18
N$257
  Top 0.254: 76.65,56.65 78.11,56.2 J25.1
  Top 0.406: 76.65,56.65 74.51,55.6 C83.P$1
N$258
  Top 0.254: 74.39,51.66 C83.P$2 | MB4.4 71.92,50.18
  Top 0.406: 74.39,51.66 71.93,51.69 71.92,50.18
N$259
  Top 0.254: C84.P$1 64.19,50.18 | 67.95,50.18 MB4.1
  Top 0.406: 64.19,50.18 67.95,50.18
N$260
  Top 0.254: C84.P$2 64.03,52.47 | 61.65,54.64 RF-BE4.1
  Top 0.406: 64.03,52.47 64.03,53.65 61.65,54.64
N$261
  Top 0.254: R45.P$2 66.45,53.94 | 70.59,50.18 MB4.3
  Top 0.406: 66.45,53.94 70.59,53.18 70.59,50.18
S$1
  Top 0.254: SW17.2 106.1,102.76
S$2
  Bottom 0.254: TÁP2.2 16.22,140.1
S$3
  Top 0.254: TÁP5.2 148.01,140.1
S$7
  Bottom 0.254: SW8.2 58.13,102.76

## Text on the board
Top: MC145152 | PLL | MB501 DIVIDER | PLL | LOW PASS FILTER
Bottom: MC145152 | PLL | MB501 DIVIDER | PLL | LOW PASS FILTER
